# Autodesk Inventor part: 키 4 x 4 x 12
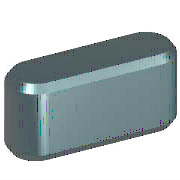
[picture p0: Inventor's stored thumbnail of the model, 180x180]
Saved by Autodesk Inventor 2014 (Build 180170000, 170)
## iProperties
IsCustomPart: 1
Created: 2012-02
Part Number: 키 4 x 4 x 12
Material: 강철, 연강
Description: 키 및 해당 키홈
Document SubType Name: Modeling
Standard: KS B 1311
Designer: mduedu
Standards Organization: KS
Language: ko-KR
Size Designation: 4 x 4 x 12
Categories: <MemberInstance><Categories><Category DisplayName="샤프트 부품" InternalName="7f7aeb1f-a693-4053-b835-cee3144e0d98" Mnemonic="SHFT"><Category DisplayName="키" Interna
Density: 7.86 g/cm^3
Mass: 1.38739 g
Surface Area: 1.94869 cm^2
Volume: 0.176513 cm^3
Appearance: 노란색
Author: mduedu
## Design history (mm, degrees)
workplane "Work Plane1"
workplane "Work Plane2"
sketch "스케치1"
  geometry: L1 (2, 2)-(10, 2); L2 (10, -2)-(2, -2); L3 (0, 9.4)-(0, -7.4) reference; L4 (-5, 0)-(30, 0) reference; L5 (12, 0)-(12, 7); A1 r 2 centre (2, 0) between (2, 2) and (2, -2); A2 r 2 centre (10, 0) between (10, -2) and (10, 2)
  constraints: 6 end point, 5 point on circle, 4 tangent, 3 point on line, 2 centre point, 1 horizontal, 1 parallel, 1 perpendicular
  dimensions: "d0" = 2 radius of A1 (= 0.5 x PB); "d13" = 2 radius of A2 (= 0.5 x PB); "d14" = 12 distance between parallel lines of L5 L3 (= NLG)
extrude "본체1" new body sketch "스케치1" taper "d3" = 0 deg; stored distance "d4" = 10
workplane "Work Plane3"
body "Solid1"
chamfer "모따기1" distance "d8" = 0.25 (= PHH); stored, may be unused: second distance "d9" = 0.25 (= PHH), angle "d15" = 45 deg
other parameters: "d1" = -2.5 (= -PNT), "d2" = 1.5 (= PH - PNT), "NLG" = 12 [user parameter; used in 3 equation terms], "PB" = 4 [user parameter; used in 2 equation terms], "PNT" = 2.5 [user parameter; used in 2 equation terms], "PH" = 4 [user parameter; used in 1 equation term], "PHH" = 0.25 [user parameter; used in 2 equation terms], "d10" = 0, "d16" = 0, "d17" = 0, "d18" = 0, "PLB2" = 12 (= NLG) [user parameter], "WDMAX" = 12 [user parameter], "PLB1" = 12 (= NLG) [user parameter], "RR" = 0.08 [user parameter], "PUEB" = 1.8 [user parameter]
